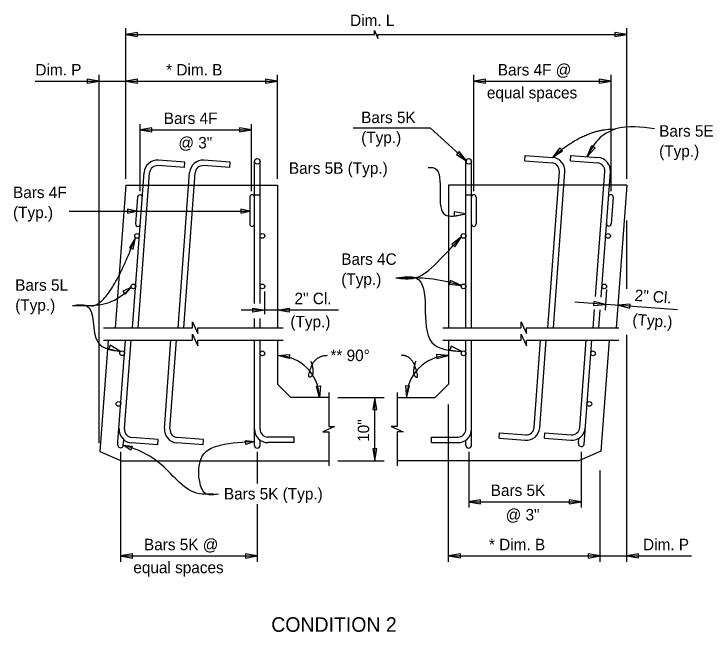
# Model space of a CAD drawing. Extents: x 0.5 to 29.5, y 0.9 to 17.7.
# Drawn here: x 10.81 to 20.03, y 9.56 to 17.7 of the extents above; entities that cross this region are included whole.
import ezdxf

# ---------------------------------------------------------------- set-up
doc = ezdxf.new("R2010")
doc.units = 0
for name, color, linetype in [('BeamConc', 7, 'Continuous'), ('Dimension', 7, 'Continuous'), ('Rebar', 7, 'Continuous'), ('TextStructures', 7, 'Continuous')]:
    doc.layers.add(name, color=color, linetype=linetype)

# ---------------------------------------------------------------- blocks, each defined once
blk = doc.blocks.new('Terminator-Arrow')
at = {"layer": 'Dimension'}
blk.add_lwpolyline([(0, 0), (-0.00041, 0.000069), (-0.00041, -0.000069)], close=True, dxfattribs=at)

msp = doc.modelspace()

# ---------------------------------------------------------------- linework, layer by layer
at = {"layer": 'BeamConc'}
for p, q in [((12.283, 15.4467), (12.1443, 13.5686)), ((12.283, 15.4467), (14.283, 15.4467)), ((14.283, 15.4467), (14.283, 13.5686)), ((18.891, 15.4467), (16.5402, 15.4467)), ((16.5402, 15.4467), (16.5402, 13.5686)), ((18.8909, 15.4467), (18.7523, 13.5686)), ((12.0498, 13.4069), (11.9413, 11.9377)), ((14.283, 13.4069), (14.283, 12.8248)), ((16.5402, 13.4069), (16.5402, 12.8247)), ((18.6577, 13.4069), (18.5494, 11.9397)), ((14.4598, 12.648), (14.283, 12.8248)), ((16.3634, 12.648), (16.5402, 12.8247)), ((14.9604, 12.648), (14.4598, 12.648)), ((15.8628, 12.648), (16.3634, 12.648)), ((11.9413, 11.9377), (12.2285, 11.8147)), ((18.5494, 11.9397), (18.2577, 11.8147)), ((12.2285, 11.8147), (14.9604, 11.8147)), ((18.2577, 11.8147), (15.8628, 11.8147))]:
    msp.add_line(p, q, dxfattribs=at)
at = {"layer": 'Dimension'}
for p, q in [((12.283, 15.5294), (12.283, 17.5191)), ((12.283, 15.5294), (12.283, 17.5191)), ((18.891, 15.5294), (18.891, 17.5191)), ((18.891, 15.5294), (18.891, 17.5191)), ((11.9323, 12.0462), (11.9323, 16.9032)), ((11.9323, 12.0462), (11.9323, 16.9032)), ((14.283, 15.5294), (14.283, 16.9032)), ((14.283, 15.5294), (14.283, 16.9032)), ((16.8735, 15.3678), (16.8735, 16.9032)), ((16.8735, 15.3678), (16.8735, 16.9032)), ((18.6834, 15.3678), (18.6834, 16.9032)), ((18.6834, 15.3678), (18.6834, 16.9032)), ((11.0869, 16.8187), (14.2829, 16.8187)), ((11.0869, 16.8187), (14.2829, 16.8187)), ((16.8734, 16.8187), (18.6833, 16.8187)), ((16.8734, 16.8187), (18.6833, 16.8187)), ((12.472, 15.3678), (12.472, 16.2542)), ((12.472, 15.3678), (12.472, 16.2542)), ((13.9408, 15.3678), (13.9408, 16.2542)), ((13.9408, 15.3678), (13.9408, 16.2542)), ((12.472, 16.1786), (13.9408, 16.1786)), ((12.472, 16.1786), (13.9408, 16.1786)), ((15.2822, 16.2054), (16.2969, 16.2054)), ((15.2822, 16.2054), (16.2969, 16.2054)), ((16.8058, 15.7974), (16.8058, 15.7974)), ((16.8058, 15.7974), (16.8058, 15.7974)), ((11.5388, 15.1046), (13.9184, 15.1046)), ((11.5388, 15.1046), (13.9184, 15.1046)), ((18.8909, 14.081), (18.8909, 14.9833)), ((18.8909, 14.081), (18.8909, 14.9833)), ((14.1164, 13.7476), (14.1164, 14.0479)), ((14.1164, 13.7476), (14.1164, 14.0479)), ((18.6251, 14.0722), (18.6049, 13.7987)), ((18.6251, 14.0722), (18.6049, 13.7987)), ((19.5617, 13.8066), (18.2052, 13.9068)), ((19.5617, 13.8066), (18.2052, 13.9068)), ((15.091, 13.8014), (13.8063, 13.8014)), ((15.091, 13.8014), (13.8063, 13.8014)), ((18.8909, 10.4848), (18.8909, 13.4741)), ((18.8909, 10.4848), (18.8909, 13.4741)), ((15.0815, 12.648), (15.6896, 12.648)), ((15.0815, 12.648), (15.6896, 12.648)), ((15.5688, 11.8147), (15.5688, 12.648)), ((15.5688, 11.8147), (15.5688, 12.648)), ((16.5402, 10.4848), (16.5402, 12.5562)), ((16.5402, 10.4848), (16.5402, 12.5562)), ((12.2141, 11.932), (12.2141, 10.4848)), ((12.2141, 11.932), (12.2141, 10.4848)), ((14.0174, 11.932), (14.0174, 11.5171)), ((14.0174, 11.932), (14.0174, 11.5171)), ((16.8058, 11.932), (16.8058, 11.2001)), ((16.8058, 11.932), (16.8058, 11.2001)), ((18.2877, 11.932), (18.2877, 11.2001)), ((18.2877, 11.932), (18.2877, 11.2001)), ((15.0815, 11.8147), (15.6896, 11.8147)), ((15.0815, 11.8147), (15.6896, 11.8147)), ((18.5402, 10.4848), (18.5402, 11.6868)), ((18.5402, 10.4848), (18.5402, 11.6868)), ((16.8058, 11.2758), (18.2877, 11.2758)), ((16.8058, 11.2758), (18.2877, 11.2758)), ((14.0174, 11.2449), (14.0174, 10.4848)), ((14.0174, 11.2449), (14.0174, 10.4848)), ((12.2141, 10.5605), (14.0174, 10.5605)), ((12.2141, 10.5605), (14.0174, 10.5605)), ((16.5402, 10.5605), (19.7458, 10.5605)), ((16.5402, 10.5605), (19.7458, 10.5605))]:
    msp.add_line(p, q, dxfattribs=at)
for points in [[(12.2829, 17.434), (15.5643, 17.434), (15.5643, 17.4857), (15.5868, 17.434), (15.6093, 17.3823), (15.6093, 17.434), (18.8908, 17.434)], [(12.2829, 17.434), (15.5643, 17.434), (15.5643, 17.4857), (15.5868, 17.434), (15.6093, 17.3823), (15.6093, 17.434), (18.8908, 17.434)], [(16.2969, 16.2054), (16.7797, 15.7654)], [(16.2969, 16.2054), (16.7797, 15.7654)], [(11.9899, 13.5686), (13.1651, 13.5686), (13.1651, 13.6461), (13.1989, 13.5686), (13.2326, 13.4911), (13.2326, 13.5686), (14.3587, 13.5686)], [(11.9899, 13.5686), (13.1651, 13.5686), (13.1651, 13.6461), (13.1989, 13.5686), (13.2326, 13.4911), (13.2326, 13.5686), (14.3587, 13.5686)], [(16.4646, 13.5686), (17.4999, 13.5686), (17.4999, 13.6461), (17.5336, 13.5686), (17.5674, 13.4911), (17.5674, 13.5686), (18.7857, 13.5686)], [(16.4646, 13.5686), (17.4999, 13.5686), (17.4999, 13.6461), (17.5336, 13.5686), (17.5674, 13.4911), (17.5674, 13.5686), (18.7857, 13.5686)], [(11.9899, 13.4069), (13.1651, 13.4069), (13.1651, 13.4844), (13.1989, 13.4069), (13.2326, 13.3294), (13.2326, 13.4069), (14.3587, 13.4069)], [(11.9899, 13.4069), (13.1651, 13.4069), (13.1651, 13.4844), (13.1989, 13.4069), (13.2326, 13.3294), (13.2326, 13.4069), (14.3587, 13.4069)], [(16.4646, 13.4069), (17.4999, 13.4069), (17.4999, 13.4844), (17.5336, 13.4069), (17.5674, 13.3294), (17.5674, 13.4069), (18.7857, 13.4069)], [(16.4646, 13.4069), (17.4999, 13.4069), (17.4999, 13.4844), (17.5336, 13.4069), (17.5674, 13.3294), (17.5674, 13.4069), (18.7857, 13.4069)], [(14.9604, 12.7151), (14.9604, 12.2651), (15.0379, 12.2651), (14.8829, 12.1976), (14.9604, 12.1976), (14.9604, 11.7476)], [(14.9604, 12.7151), (14.9604, 12.2651), (15.0379, 12.2651), (14.8829, 12.1976), (14.9604, 12.1976), (14.9604, 11.7476)], [(15.8628, 12.7151), (15.8628, 12.2651), (15.7853, 12.2651), (15.9403, 12.1976), (15.8628, 12.1976), (15.8628, 11.7476)], [(15.8628, 12.7151), (15.8628, 12.2651), (15.7853, 12.2651), (15.9403, 12.1976), (15.8628, 12.1976), (15.8628, 11.7476)]]:
    msp.add_lwpolyline(points, dxfattribs=at)
for points in [[(18.3696, 15.8241), (18.4316, 15.9698), (18.4761, 15.9413)], [(18.3696, 15.8241), (18.4316, 15.9698), (18.4761, 15.9413)], [(16.7797, 15.7655), (16.6821, 15.8902), (16.6464, 15.8511)], [(16.7797, 15.7655), (16.6821, 15.8902), (16.6464, 15.8511)], [(17.9105, 15.8135), (18.0437, 15.8993), (18.008, 15.9384)], [(17.9105, 15.8135), (18.0437, 15.8993), (18.008, 15.9384)], [(12.4249, 15.1046), (12.3077, 15.1311), (12.3077, 15.0782)], [(12.4249, 15.1046), (12.3077, 15.1311), (12.3077, 15.0782)], [(13.9185, 15.1046), (13.8013, 15.1311), (13.8013, 15.0782)], [(13.9185, 15.1046), (13.8013, 15.1311), (13.8013, 15.0782)], [(16.7693, 15.0688), (16.6132, 15.0952), (16.6132, 15.0423)], [(16.7693, 15.0688), (16.6132, 15.0952), (16.6132, 15.0423)], [(12.4102, 14.7579), (12.3302, 14.6212), (12.3797, 14.6025)], [(12.4102, 14.7579), (12.3302, 14.6212), (12.3797, 14.6025)], [(16.7103, 14.7657), (16.5834, 14.6708), (16.6218, 14.6344)], [(16.7103, 14.7657), (16.5834, 14.6708), (16.6218, 14.6344)], [(16.7099, 14.1268), (16.5662, 14.1935), (16.5522, 14.1424)], [(16.7099, 14.1268), (16.5662, 14.1935), (16.5522, 14.1424)], [(12.3552, 14.0992), (12.2446, 14.0524), (12.2755, 14.0094)], [(12.3552, 14.0992), (12.2446, 14.0524), (12.2755, 14.0094)], [(18.6107, 13.8769), (18.4569, 13.9148), (18.453, 13.862)], [(18.6107, 13.8769), (18.4569, 13.9148), (18.453, 13.862)], [(18.7771, 13.8646), (18.9309, 13.8267), (18.9348, 13.8795)], [(18.7771, 13.8646), (18.9309, 13.8267), (18.9348, 13.8795)], [(12.2135, 13.2554), (12.0785, 13.3383), (12.0587, 13.2892)], [(12.2135, 13.2554), (12.0785, 13.3383), (12.0587, 13.2892)], [(16.716, 13.2534), (16.5745, 13.3246), (16.5589, 13.274)], [(16.716, 13.2534), (16.5745, 13.3246), (16.5589, 13.274)], [(14.283, 13.2014), (14.4409, 13.2145), (14.4364, 13.1617)], [(14.283, 13.2014), (14.4409, 13.2145), (14.4364, 13.1617)], [(16.5402, 13.2014), (16.3823, 13.2145), (16.3868, 13.1617)], [(16.5402, 13.2014), (16.3823, 13.2145), (16.3868, 13.1617)], [(14.8378, 12.6461), (14.7967, 12.7991), (14.8493, 12.8041)], [(14.8378, 12.6461), (14.7967, 12.7991), (14.8493, 12.8041)], [(15.9854, 12.6461), (16.0265, 12.7991), (15.9739, 12.8041)], [(15.9854, 12.6461), (16.0265, 12.7991), (15.9739, 12.8041)], [(15.5688, 12.648), (15.5424, 12.4918), (15.5953, 12.4918)], [(15.5688, 12.648), (15.5424, 12.4918), (15.5953, 12.4918)], [(13.9803, 12.0701), (13.8668, 12.0311), (13.861, 12.0837)], [(13.9803, 12.0701), (13.8668, 12.0311), (13.861, 12.0837)], [(12.2504, 12.0215), (12.3696, 12.0069), (12.3518, 11.9571)], [(12.2504, 12.0215), (12.3696, 12.0069), (12.3518, 11.9571)], [(15.5688, 11.8147), (15.5953, 11.9709), (15.5424, 11.9709)], [(15.5688, 11.8147), (15.5953, 11.9709), (15.5424, 11.9709)]]:
    msp.add_lwpolyline(points, close=True, dxfattribs=at)
for centre, start, end in [((14.2787, 12.6422), 0.39914, 89.54996), ((14.2787, 12.6422), 0.39914, 89.54996), ((16.5446, 12.6422), 90.45004, 179.60086), ((16.5446, 12.6422), 90.45004, 179.60086)]:
    msp.add_arc(centre, 0.5592, start, end, dxfattribs=at)
for points in [[(19.2565, 16.1887), (18.7421, 16.1887), (18.512, 16.0462), (18.3696, 15.8241)], [(19.2565, 16.1887), (18.7421, 16.1887), (18.512, 16.0462), (18.3696, 15.8241)], [(16.2694, 15.6807), (16.33, 15.6807), (16.4798, 15.0688), (16.7693, 15.0688)], [(16.2694, 15.6807), (16.33, 15.6807), (16.4798, 15.0688), (16.7693, 15.0688)], [(15.845, 14.2258), (16.0971, 14.2258), (16.4313, 14.4725), (16.7103, 14.7657)], [(15.845, 14.2258), (16.0971, 14.2258), (16.4313, 14.4725), (16.7103, 14.7657)], [(15.8505, 14.2258), (16.1094, 14.2258), (16.3212, 13.3746), (16.716, 13.2534)], [(15.8505, 14.2258), (16.1094, 14.2258), (16.3212, 13.3746), (16.716, 13.2534)], [(15.8779, 14.2258), (16.1957, 14.2258), (16.5682, 14.1655), (16.7099, 14.1268)], [(15.8779, 14.2258), (16.1957, 14.2258), (16.5682, 14.1655), (16.7099, 14.1268)], [(11.5809, 13.8621), (11.8006, 13.8621), (12.1012, 13.9171), (12.3552, 14.0992)], [(11.5809, 13.8621), (11.8006, 13.8621), (12.1012, 13.9171), (12.3552, 14.0992)], [(11.5896, 13.8621), (11.763, 13.8621), (11.9177, 13.3746), (12.2135, 13.2554)], [(11.5896, 13.8621), (11.763, 13.8621), (11.9177, 13.3746), (12.2135, 13.2554)], [(13.4386, 11.3767), (13.3318, 11.3767), (13.2907, 11.3767), (12.7895, 11.7303), (12.4745, 11.9413), (12.2505, 12.0215)], [(13.4386, 11.3767), (13.3318, 11.3767), (13.2907, 11.3767), (12.7895, 11.7303), (12.4745, 11.9413), (12.2505, 12.0215)], [(13.507, 11.3767), (13.3455, 11.3767), (13.2578, 11.5412), (13.3482, 11.9413), (13.529, 12.0208), (13.9804, 12.0701)], [(13.507, 11.3767), (13.3455, 11.3767), (13.2578, 11.5412), (13.3482, 11.9413), (13.529, 12.0208), (13.9804, 12.0701)]]:
    msp.add_spline(points, degree=3, dxfattribs=at)
for points in [[(17.9107, 15.8136), (18.3208, 16.1884), (18.731, 16.1884)], [(17.9107, 15.8136), (18.3208, 16.1884), (18.731, 16.1884)], [(11.8247, 13.8552), (12.0685, 13.8552), (12.4102, 14.7579)], [(11.8247, 13.8552), (12.0685, 13.8552), (12.4102, 14.7579)], [(14.7235, 13.1287), (14.7808, 12.9568), (14.67, 12.8881), (14.7827, 13.2051), (14.9457, 13.2051)], [(14.7235, 13.1287), (14.7808, 12.9568), (14.67, 12.8881), (14.7827, 13.2051), (14.9457, 13.2051)], [(16.1068, 13.1287), (16.0496, 12.9568), (16.1603, 12.8881), (16.0476, 13.2051), (15.9216, 13.2051)], [(16.1068, 13.1287), (16.0496, 12.9568), (16.1603, 12.8881), (16.0476, 13.2051), (15.9216, 13.2051)]]:
    msp.add_open_spline(points, degree=2, dxfattribs=at)
at = {"layer": 'Rebar'}
for p, q in [((13.0618, 15.7527), (12.7149, 15.7783)), ((13.6618, 15.7527), (13.3149, 15.7783)), ((17.5471, 15.7674), (17.5525, 15.8401)), ((17.5471, 15.7674), (17.9053, 15.7409)), ((17.5525, 15.8401), (17.9107, 15.8136)), ((18.1471, 15.7674), (18.1525, 15.8401)), ((18.1471, 15.7674), (18.5053, 15.7409)), ((18.1525, 15.8401), (18.5107, 15.8136)), ((13.0564, 15.68), (12.7095, 15.7056)), ((13.0564, 15.68), (13.0618, 15.7527)), ((13.6564, 15.68), (13.3095, 15.7056)), ((13.6564, 15.68), (13.6618, 15.7527)), ((13.981, 13.8896), (13.981, 15.7598)), ((14.0539, 13.8896), (14.0539, 15.7598)), ((16.7693, 13.5686), (16.7693, 15.7598)), ((16.8422, 13.5686), (16.8422, 15.7598)), ((12.3741, 13.5686), (12.5252, 15.6148)), ((12.4472, 13.5686), (12.5979, 15.6094)), ((12.9741, 13.5686), (13.1252, 15.6148)), ((13.0472, 13.5686), (13.1979, 15.6094)), ((17.8494, 13.5686), (18.0015, 15.6293)), ((17.9225, 13.5686), (18.0743, 15.624)), ((18.4797, 13.9789), (18.6015, 15.6293)), ((18.5522, 13.9704), (18.6743, 15.624)), ((13.981, 15.3217), (14.0539, 15.3217)), ((16.7693, 15.3217), (16.8422, 15.3217)), ((12.4386, 15.2904), (12.4125, 14.9372)), ((13.9185, 15.2904), (13.9185, 14.9363)), ((16.9047, 15.2904), (16.9047, 14.9363)), ((18.7123, 15.2904), (18.6862, 14.9372)), ((18.4494, 13.5686), (18.4671, 13.8082)), ((18.5225, 13.5686), (18.5398, 13.8033)), ((13.981, 13.5686), (13.981, 13.6917)), ((14.0539, 13.5686), (14.0539, 13.6917)), ((12.1804, 12.0632), (12.2796, 13.4069)), ((12.2662, 12.2345), (12.3527, 13.4069)), ((12.7934, 12.2399), (12.8796, 13.4069)), ((12.8662, 12.2345), (12.9527, 13.4069)), ((13.981, 12.0542), (13.981, 13.4069)), ((14.0539, 12.2313), (14.0539, 13.4069)), ((16.7693, 12.2313), (16.7693, 13.4069)), ((16.8422, 12.0178), (16.8422, 13.4069)), ((17.6698, 12.2545), (17.7549, 13.4069)), ((17.7425, 12.2491), (17.828, 13.4069)), ((18.2698, 12.2545), (18.3549, 13.4069)), ((18.3268, 12.0361), (18.428, 13.4069)), ((17.2059, 12.1111), (17.2112, 12.1838)), ((17.2112, 12.1838), (17.5582, 12.1582)), ((17.8059, 12.1111), (17.8112, 12.1838)), ((17.8112, 12.1838), (18.1582, 12.1582)), ((12.2504, 12.0215), (12.2556, 12.0917)), ((12.7093, 12.0973), (12.3624, 12.1229)), ((12.704, 12.0246), (12.7093, 12.0973)), ((13.3093, 12.0973), (12.9624, 12.1229)), ((13.304, 12.0246), (13.3093, 12.0973)), ((14.0539, 12.0178), (14.0539, 12.0881)), ((14.506, 12.1271), (14.1581, 12.1271)), ((14.506, 12.0542), (14.506, 12.1271)), ((16.3172, 12.1271), (16.6651, 12.1271)), ((16.3172, 12.0542), (16.3172, 12.1271)), ((16.7693, 12.0178), (16.7693, 12.0881)), ((17.2059, 12.1111), (17.5528, 12.0855)), ((17.8059, 12.1111), (18.1528, 12.0855)), ((18.254, 12.0415), (18.2592, 12.1116)), ((12.1777, 12.0269), (12.1804, 12.0632)), ((12.704, 12.0246), (12.357, 12.0502)), ((13.304, 12.0246), (12.957, 12.0502)), ((13.981, 12.0178), (13.981, 12.0542)), ((14.506, 12.0542), (14.1581, 12.0542)), ((16.3172, 12.0542), (16.6651, 12.0542))]:
    msp.add_line(p, q, dxfattribs=at)
for centre, radius in [((14.0174, 15.7609), 0.0365), ((16.8058, 15.7609), 0.0365), ((12.4323, 14.78), 0.0312), ((14.0851, 14.78), 0.0312), ((16.7381, 14.78), 0.0312), ((18.6432, 14.78), 0.0312), ((12.3831, 14.1133), 0.0312), ((14.0851, 14.1133), 0.0312), ((16.7381, 14.1133), 0.0312), ((18.594, 14.1133), 0.0312), ((12.2356, 13.2333), 0.0312), ((14.0851, 13.2313), 0.0312), ((16.7381, 13.2313), 0.0312), ((18.4463, 13.2313), 0.0312), ((12.1862, 12.5655), 0.0312), ((18.397, 12.5646), 0.0312)]:
    msp.add_circle(centre, radius, dxfattribs=at)
for centre, radius, start, end in [((12.7018, 15.6017), 0.1771, 85.77683, 175.77683), ((13.3018, 15.6017), 0.1771, 85.77683, 175.77683), ((17.8976, 15.637), 0.1771, 355.77659, 85.77659), ((18.4976, 15.637), 0.1771, 355.77659, 85.77659), ((12.7018, 15.6017), 0.1042, 85.77683, 175.77683), ((13.3018, 15.6017), 0.1042, 85.77683, 175.77683), ((17.8976, 15.637), 0.1042, 355.77659, 85.77659), ((18.4976, 15.637), 0.1042, 355.77659, 85.77659), ((12.4697, 15.2881), 0.0312, 355.77683, 175.77683), ((13.9497, 15.2904), 0.0312, 0, 180), ((16.8735, 15.2904), 0.0312, 0, 180), ((18.6811, 15.2927), 0.0312, 355.77659, 175.77659), ((12.4437, 14.9349), 0.0312, 175.77683, 355.77683), ((13.9497, 14.9363), 0.0312, 180, 0), ((16.8735, 14.9363), 0.0312, 180, 0), ((18.6551, 14.9395), 0.0312, 175.77659, 355.77659), ((12.3722, 12.2248), 0.1752, 175.04658, 265.04658), ((12.3701, 12.2268), 0.1042, 175.77683, 265.77683), ((12.9701, 12.2268), 0.1771, 175.77683, 265.77683), ((12.9701, 12.2268), 0.1042, 175.77683, 265.77683), ((14.1581, 12.2313), 0.1771, 180, 270), ((14.1581, 12.2313), 0.1042, 180, 270), ((16.6651, 12.2313), 0.1042, 270, 360), ((16.6651, 12.2313), 0.1771, 270, 360), ((17.5659, 12.2621), 0.1771, 265.77659, 355.77659), ((17.5659, 12.2621), 0.1042, 265.77659, 355.77659), ((18.1659, 12.2621), 0.1771, 265.77659, 355.77659), ((18.1659, 12.2621), 0.1042, 265.77659, 355.77659), ((12.2141, 12.0242), 0.0365, 175.77683, 355.77683), ((14.0174, 12.0178), 0.0365, 180, 0), ((16.8058, 12.0178), 0.0365, 180, 0), ((18.2904, 12.0388), 0.0365, 175.77659, 355.77659)]:
    msp.add_arc(centre, radius, start, end, dxfattribs=at)

# ---------------------------------------------------------------- block references
at = {"layer": 'Dimension', "xscale": 381, "rotation": 180}
for p, yscale in [((12.2828, 17.4334), 384.0238095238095), ((12.2828, 17.4334), 384.0238095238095), ((12.2828, 16.8182), 384.0238095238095), ((12.2828, 16.8182), 384.0238095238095), ((16.8732, 16.8183), 384.0238095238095), ((16.8732, 16.8183), 384.0238095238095), ((12.4719, 16.1783), 384.0238095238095), ((12.4719, 16.1783), 384.0238095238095), ((14.2829, 13.8011), -384.0238095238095), ((14.2829, 13.8011), -384.0238095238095), ((16.8056, 11.2754), 384.0238095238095), ((16.8056, 11.2754), 384.0238095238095), ((12.2138, 10.5601), 384.0238095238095), ((12.2138, 10.5601), 384.0238095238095), ((16.54, 10.5602), 384.0238095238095), ((16.54, 10.5602), 384.0238095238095), ((18.8909, 10.5602), 384.0238095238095), ((18.8909, 10.5602), 384.0238095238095)]:
    msp.add_blockref('Terminator-Arrow', p, dxfattribs=dict(at, yscale=yscale))
at = {"layer": 'Dimension', "xscale": 381}
for p, yscale in [((18.8907, 17.4335), 384.0238095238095), ((18.8907, 17.4335), 384.0238095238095), ((11.932, 16.8182), 384.0238095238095), ((11.932, 16.8182), 384.0238095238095), ((14.2828, 16.8182), 384.0238095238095), ((14.2828, 16.8182), 384.0238095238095), ((18.6831, 16.8183), 384.0238095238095), ((18.6831, 16.8183), 384.0238095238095), ((13.9406, 16.1783), 384.0238095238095), ((13.9406, 16.1783), 384.0238095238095), ((14.1163, 13.8011), -384.0238095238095), ((14.1163, 13.8011), -384.0238095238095), ((18.2875, 11.2754), 384.0238095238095), ((18.2875, 11.2754), 384.0238095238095), ((14.0172, 10.5601), 384.0238095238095), ((14.0172, 10.5601), 384.0238095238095), ((18.5401, 10.5601), 384.0238095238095), ((18.5401, 10.5601), 384.0238095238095)]:
    msp.add_blockref('Terminator-Arrow', p, dxfattribs=dict(at, yscale=yscale))

# ---------------------------------------------------------------- texts
at = {"layer": 'Dimension'}
for s, p in [('Bars 5K', (15.3879, 16.2659)), ('Bars 5E', (19.3179, 16.0871)), ('(Typ.)', (15.3879, 16.0019)), ('(Typ.)', (19.3179, 15.8231)), ('Bars 4F', (10.7962, 15.2776)), ('(Typ.)', (10.7962, 15.0136)), ('Bars 4C', (15.1255, 14.3979)), ('(Typ.)', (15.1255, 14.1339)), ('Bars 5L', (10.8249, 14.0561)), ('(Typ.)', (10.8249, 13.7921))]:
    msp.add_text(s, height=0.1512, dxfattribs=at).set_placement(p)
at = {"layer": 'TextStructures'}
for s, height, p in [('Dim. L', 0.1512, (15.2421, 17.5452)), ('Dim. P', 0.1512, (11.0921, 16.8938)), ('* Dim. B', 0.1512, (12.8161, 16.8938)), ('Bars 4F @', 0.1512, (17.1901, 16.8939)), ('equal spaces', 0.1512, (17.0457, 16.5918)), ('Bars 4F', 0.1512, (12.7845, 16.2539)), ('@ 3"', 0.1512, (12.9777, 15.9318)), ('Bars 5B (Typ.)', 0.1512, (14.4346, 15.5978)), ('2" Cl.', 0.1512, (14.5093, 13.8795)), ('(Typ.)', 0.1512, (14.4546, 13.5743)), ('** 90°', 0.1512, (14.9823, 13.1292)), ('Bars 5K (Typ.)', 0.1512, (13.5775, 11.3052)), ('Bars 5K', 0.1512, (17.0965, 11.351)), ('@ 3"', 0.1512, (17.2944, 11.0289)), ('Bars 5K @', 0.1512, (12.523, 10.6357)), ('* Dim. B', 0.1512, (17.0734, 10.6357)), ('Dim. P', 0.1512, (19.1059, 10.6357)), ('equal spaces', 0.1512, (12.3831, 10.3335)), ('CONDITION 2', 0.192, (14.202, 9.5608))]:
    msp.add_text(s, height=height, dxfattribs=at).set_placement(p)
for s, rotation, p in [('2" Cl.', 355.77659, (18.9903, 13.9235)), ('(Typ.)', 355.77659, (18.9614, 13.6053)), ('10"', 90, (15.4931, 12.0644))]:
    msp.add_text(s, height=0.1512, rotation=rotation, dxfattribs=at).set_placement(p)

doc.saveas('drawing.dxf')
